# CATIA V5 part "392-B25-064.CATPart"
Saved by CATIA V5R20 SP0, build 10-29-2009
Part number: 392-B25-064
Definition: NONE
Nomenclature: 392-B25-064
Source: Unknown
Description: 392-B25-064
Bounding box of the stored display mesh (mm): x 0 to 64, y -12.36 to 12.36, z -12.25 to 12.064
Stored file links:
  C:\Users\Utente\Desktop\IO LAVORO\3D X SITO CF\X SITO\3D files 392B\392-B25-064.CATPart
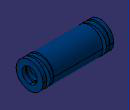
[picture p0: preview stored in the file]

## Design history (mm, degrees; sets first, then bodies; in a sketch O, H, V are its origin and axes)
Body1 "392-B25-064" (main body)
  Solid1: solid without history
